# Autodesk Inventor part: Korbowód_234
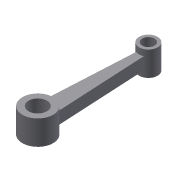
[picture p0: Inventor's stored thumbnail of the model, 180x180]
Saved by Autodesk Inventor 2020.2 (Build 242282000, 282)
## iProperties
Created: 2005-10
Part Number: Korbowód_234
Document SubType Name: Modeling
Designer: F.Stasiak
Density: 1 g/cm^3
Material: Ogólny
Appearance: Domyślna
Manager: www.cadconsulting.pl
Company: Fabian Stasiak CAD Consulting
Subject: Zbiór ćwiczeń. Autodesk Inventor 2020. Kurs podstawowy
Author: F.Stasiak
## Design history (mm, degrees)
sketch "Szkic1"
  geometry: L1 (0.611, 16.63)-(1.389, 2.079); L2 (-0.611, 16.63)-(-1.389, 2.079); C1 r 1 at (0, 18); C2 r 1.5 at (0, 0); A1 r 1.5 centre (0, 18) between (0.611, 16.63) and (-0.611, 16.63); A2 r 2.5 centre (0, 0) between (1.389, 2.079) and (-1.389, 2.079)
  constraints: 4 centre point, 4 end point, 4 point on circle
  dimensions: "d1" = 18 distance of C1.centre A2.centre; "d3" = 6.11792 deg angle of L2 L1; "d5" = 5 diameter of A2; "d7" = 3 diameter of C2; "d9" = 2 diameter of C1; "d11" = 3 diameter of A1
extrude "Wyciągnięcie proste1" new body sketch "Szkic1" stored distance "d12" = 4; taper "d13" = 0 deg
extrude "Wyciągnięcie proste2" join sketch "Szkic1" stored distance "d14" = 2; taper "d15" = 0 deg
node "Bryła1"
node "Korpusy bryłowe"
node "Korpusy powierzchniowe"
other parameters: "d0" = 18 (derived), "d2" = 1.06778 (derived), "d4" = 5 (derived), "d6" = 3 (derived), "d8" = 2 (derived), "d10" = 3 (derived)
